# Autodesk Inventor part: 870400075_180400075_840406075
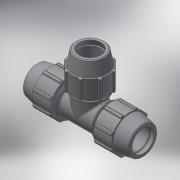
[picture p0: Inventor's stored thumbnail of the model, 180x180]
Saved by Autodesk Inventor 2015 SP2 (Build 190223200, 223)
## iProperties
Created: 2017-02
Part Number: 870400075_180400075_840406075
Material: Generic
Description: PLASSON TEE 75-75-75
Document SubType Name: Modeling
Designer: KIM
Mass: 2642.84 g
Surface Area: 3396.39 cm^2
Volume: 2642.84 cm^3
Density: 1 g/cm^3
Appearance: Default
Author: KIM
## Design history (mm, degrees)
derived "87040.ipt"
feature "Solid1::87040.ipt"
tag "TaggingFeature1"
body "Solid1"
other parameters: "d2" = 75, "d4" = 15.16667, "d5" = 45.5, "d7" = 132, "d13" = 120 deg, "d14" = 97.5, "d15" = 12 deg, "d18" = 3.75, "d19" = 35 deg, "d20" = 17.5 deg, "d21" = 122.76, "d23" = 0, "d25" = 360 deg, "d27" = 2.64, "d42" = 63.7, "d43" = 3.96, "d46" = 2.25, "d63" = 137, "d67" = 99, "d76" = 75, "d77" = 132, "d78" = 12 deg, "d79" = 182, "d80" = 120 deg, "d81" = 97.5, "d82" = 15.16667, "d85" = 99, "d87" = 6.06667, "d88" = 6.06667, "d89" = 45.5, "d90" = 63.7, "d98" = 122.76, "d99" = 35 deg, "d100" = 17.5 deg, "d102" = 0, "d103" = 2.64, "d107" = 360 deg, "d109" = 2.25, "d112" = 3.75, "d118" = 360 deg, "d121" = 0, "d128" = 364, "d131" = 67.5, "d132" = 67.5, "d133" = 137, "d134" = 2.74, "d152" = 0, "d154" = 0, "d156" = 0, "d158" = 0, "d163" = 13.9, "d165" = 15.27, "d166" = 94.05, "d167" = 94.05, "d168" = 5.09, "d169" = 108.9, "d170" = 2.545, "d171" = 3.8175, "d172" = 108.9, "d173" = 4.63333, "d174" = 2.31667, "d175" = 3.475, "d176" = 1.5, "d177" = 3.75, "d_" = 75, "E_" = 132, "A_" = 182, "l_" = 137, "H_" = 364, "d162" = 27.8, "d164" = 30.54
